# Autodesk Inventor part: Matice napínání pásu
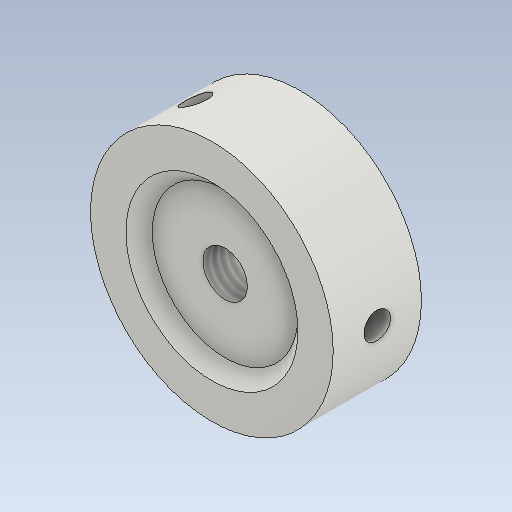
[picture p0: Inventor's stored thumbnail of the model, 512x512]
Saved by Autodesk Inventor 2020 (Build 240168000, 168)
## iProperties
Created: 2025-03
Part Number: Matice napínání pásu
Material: Ocel
Document SubType Name: Modeling
Designer: doma
Density: 7.85 g/cm^3
Appearance: Ocel
Mass: 327.9 g
Surface Area: 95.8433 cm^2
Volume: 41.7706 cm^3
Author: doma
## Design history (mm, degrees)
sketch "Náčrt1"
  geometry: C1 r 27.5 at (0, 0); 1 further point
  constraints: 1 centre point, 1 coincident
  dimensions: "d0" = 55 diameter of C1
extrude "Vysunutí1" new body sketch "Náčrt1" stored distance "d1" = 20; taper "d2" = 0 deg
sketch "Náčrt2"
  geometry: C1 r 19.5 at (0, 0); 1 further point
  constraints: 1 centre point, 1 coincident
  dimensions: "d3" = 39 diameter of C1
extrude "Vysunutí2" cut sketch "Náčrt2" distance "d4" = 3; taper "d5" = 0 deg
chamfer "Zkosení1" distance "d6" = 3; stored, may be unused: second distance "d7" = 2, angle "d8" = 45 deg
sketch "Náčrt3"
  geometry: 2 further points
hole "Díra1" sketch "Náčrt3" at (0, 0) diameter "d9" = 10.106; stored, may be unused: countersink angle "d13" = 90 deg, drill point angle "d15" = 118 deg; dims "d10" = 24, "d11" = 4, "d12" = 2, "d14" = 8
node "Pracovní bod1"
hole "Díra2" diameter "d19" = 6; stored, may be unused: countersink angle "d23" = 90 deg, drill point angle "d25" = 118 deg; dims "d20" = 10, "d21" = 4, "d22" = 2, "d24" = 15, "d29" = 10, "d30" = 10
pattern_circular "Kruhové pole1" dims angle "d27" = 360 deg
node "Těleso1"
